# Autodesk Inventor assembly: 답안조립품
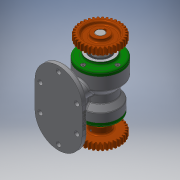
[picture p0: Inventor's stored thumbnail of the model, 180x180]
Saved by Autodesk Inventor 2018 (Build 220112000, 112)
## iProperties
Created: 2020-01
Part Number: 답안조립품
Document SubType Name: Assembly
Designer: Administrator
Author: Administrator
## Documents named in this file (12)
- C:\Users\Administrator\Desktop\700104V1041\답안조립품.iam
- C:\Users\Administrator\Desktop\700104V1041\본체.ipt
- C:\Users\Administrator\Desktop\700104V1041\축.ipt
- C:\Users\Administrator\Desktop\700104V1041\스퍼기어.ipt
- C:\Users\Administrator\Desktop\700104V1041\멈춤나사 M3.ipt
- C:\Users\Administrator\Desktop\700104V1041\Ű 5 x 5 x 18.ipt
- C:\Users\Administrator\Desktop\700104V1041\베어링 6205.ipt
- C:\Users\Administrator\Desktop\700104V1041\앞커버.ipt
- C:\Users\Administrator\Desktop\700104V1041\베어링 6203.ipt
- C:\Users\Administrator\Desktop\700104V1041\뒤커버.ipt
- C:\Users\Administrator\Desktop\700104V1041\볼트 M4.ipt
- C:\Users\Administrator\Desktop\700104V1041\오일 실 25 38 8.ipt
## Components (2 placed, 1 different names)
1. Ű 5 x 5 x 18:1
2. Ű 5 x 5 x 18:2 — 각도:1
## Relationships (1: Angle 1)
- 각도:1 [Angle]: Ű 5 x 5 x 18:2
